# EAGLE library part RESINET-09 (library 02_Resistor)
Resistor Network(9) 9 peaces
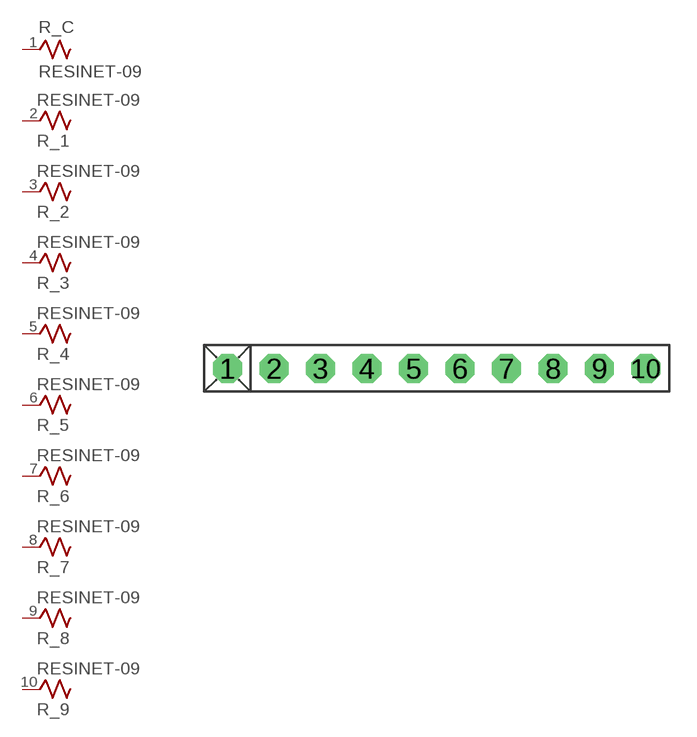
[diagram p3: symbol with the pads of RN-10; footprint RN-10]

Designator prefix R; gates _C=RESINET-COM _1=RESINET-X _2=RESINET-X _3=RESINET-X _4=RESINET-X _5=RESINET-X _6=RESINET-X _7=RESINET-X _8=RESINET-X _9=RESINET-X

## RESINET-09  [RN-10]
1  _C:1  pas
2  _1:1  pas
3  _2:1  pas
4  _3:1  pas
5  _4:1  pas
6  _5:1  pas
7  _6:1  pas
8  _7:1  pas
9  _8:1  pas
10  _9:1  pas

## Footprint RN-10 (pad centres in mm)
Resistor Network(9) 9 peaces
drill 0.813 pad 1.6 octagon: 1 -11.43,0; 2 -8.89,0; 3 -6.35,0; 4 -3.81,0; 5 -1.27,0; 6 1.27,0; 7 3.81,0; 8 6.35,0; 9 8.89,0; 10 11.43,0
